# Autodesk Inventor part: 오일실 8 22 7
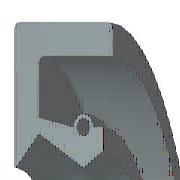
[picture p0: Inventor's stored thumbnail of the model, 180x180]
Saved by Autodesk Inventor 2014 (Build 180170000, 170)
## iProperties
IsCustomPart: 1
Created: 2012-02
Part Number: 오일실 8 22 7
Material: 고무
Description: 오일-실
Document SubType Name: Modeling
Standard: KS B 2804
Designer: mduedu
Standards Organization: KS
Language: ko-KR
Size Designation: D - 8 22 7
Categories: <MemberInstance><Categories><Category DisplayName="샤프트 부품" InternalName="7f7aeb1f-a693-4053-b835-cee3144e0d98" Mnemonic="SHFT"><Category DisplayName="실링" Intern
Density: 0.93 g/cm^3
Mass: 1.28441 g
Surface Area: 18.2787 cm^2
Volume: 1.38108 cm^3
Appearance: 고무 - 검은색 - 버전 1.1
Author: mduedu
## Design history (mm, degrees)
revolve "본체" stored, may be unused: angle "d17" = 90 deg
revolve "스프링1" stored, may be unused: angle "d18" = 90 deg
body "Solid1"
sketch "스케치1"
  geometry: L1 (0, 11)-(7, 11); L2 (7, 9.25)-(1.75, 9.25); L3 (1.75, 5.75)-(4.9, 4); L4 (4.9, 4)-(0, 4); L5 (0, 0)-(9.586, 0) reference; L6 (4.9, 4)-(6.3, 4.875); L7 (0, 18)-(0, -3) reference; L8 (-1.941, 0)-(11.507, 0) reference; L9 (4.2, 6.1)-(1.75, 6.59); L10 (1.75, 6.59)-(1.75, 9.25); L11 (0, 11)-(0, 4.088); L12 (4.9, 4)-(0, 4); L13 (1.75, 5.75)-(0.152, 4.028); L14 (7, 11)-(7, 9.25); L15 (5.6, 6.1)-(6.3, 6.1); L16 (6.3, 6.1)-(6.3, 4.875); C1 r 0.455 at (4.9, 6.1); A1 r 0.7 centre (4.9, 6.1) between (5.6, 6.1) and (4.2, 6.1); A2 r 0.088 centre (0.088, 4.088) between (0, 4.088) and (0.152, 4.028); 1 further point
  constraints: 28 end point, 5 horizontal alignment, 5 point on line, 4 point on circle, 4 vertical alignment, 3 centre point, 3 tangent, 2 collinear, 2 horizontal, 2 perpendicular, 1 coincident, 1 parallel
  dimensions: "d0" = 22 diameter of L1 L5 (= SD2); "d1" = 1.75 distance of L1.end L2.start (= SD); "d2" = 0.91 diameter of C1 (= SPDI); "d3" = 1.4 diameter of A1 (= SPDA); "d4" = 8 diameter of L3.end L5 (= NND); "d5" = 11.5 diameter of L3.start L5 (= TKDM); "d7" = 13.18 diameter of L9.end L5 (= TKDM + 0.24 x SWDT); "d8" = 1.75 distance between parallel lines of L11 L10 (= SD); "d9" = 4.9 distance from line of L11 C1.centre (= SPDST); "d10" = 12.2 diameter of C1.centre L5 (= HLDM); "d11" = 0.0875 radius of A2 (= 0.25 x LAB); "d12" = 6.3 distance between parallel lines of L11 L16 (= SDI); "d13" = 9.75 diameter of L6.end L5 (= ABDM); "d14" = 7 distance from line of L11 L1.end (= SWDT)
fillet "모깎기1" dims "d6" = 0.3 (= RR)
other parameters: "SD2" = 22 [user parameter; used in 1 equation term], "SWDT" = 7 [user parameter; used in 2 equation terms], "RR" = 0.3 [user parameter; used in 1 equation term], "SD" = 1.75 [user parameter; used in 2 equation terms], "NND" = 8 [user parameter; used in 1 equation term], "SPDA" = 1.4 [user parameter; used in 1 equation term], "SPDI" = 0.91 [user parameter; used in 1 equation term], "TKDM" = 11.5 [user parameter; used in 2 equation terms], "HLDM" = 12.2 [user parameter; used in 1 equation term], "ABDM" = 9.75 [user parameter; used in 1 equation term], "SDI" = 6.3 [user parameter; used in 1 equation term], "SPDST" = 4.9 [user parameter; used in 1 equation term], "LAB" = 0.35 [user parameter; used in 1 equation term], "d15" = 0, "d16" = 0, "d19" = 0
